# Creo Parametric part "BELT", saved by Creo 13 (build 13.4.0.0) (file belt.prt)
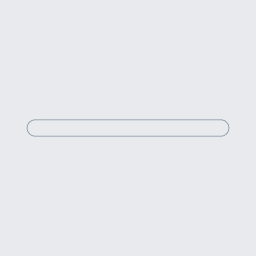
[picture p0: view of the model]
Units: millimeter Newton Second (mmNs); MM, TONNE, SECS

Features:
  1. datum plane "RIGHT"
  2. datum plane "TOP"
  3. datum plane "FRONT"
  4. coordinate system
  5. protrusion
  6. pattern
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
Surfaces: 6 plane, 4 cylinder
